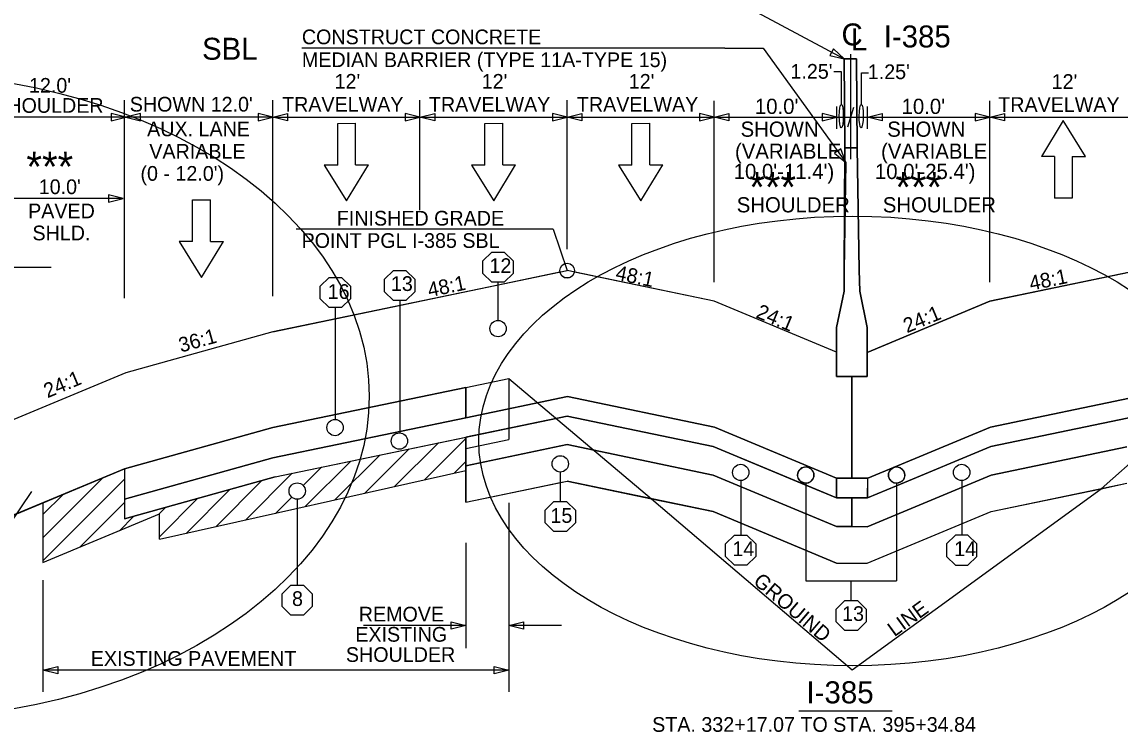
# Model space of a CAD drawing. Extents: x 4832 to 5477, y 4935 to 5220.
# Drawn here: x 5121.8 to 5211.3, y 5127.8 to 5185.7 of the extents above; entities that cross this region are included whole.
import ezdxf

# ---------------------------------------------------------------- set-up
doc = ezdxf.new("R2010")
doc.units = 0
for name, color, linetype in [('CLS_Clear_Zone', 7, 'Continuous'), ('Level 2', 7, 'Continuous'), ('RD_QTY_Milling', 7, 'Continuous'), ('RD_QTY_Miscl_1', 7, 'Continuous'), ('RD_SHT_Typical', 7, 'Continuous'), ('RD_TX_Misc1', 7, 'Continuous'), ('RD_TX_TypSect', 7, 'Continuous'), ('RD_XS_ExGround', 7, 'Continuous'), ('RD_XS_ExPaveRet', 7, 'Continuous'), ('RD_XS_PaveShd', 7, 'Continuous'), ('TERMINATOR', 7, 'Continuous'), ('typical_on', 7, 'Continuous')]:
    doc.layers.add(name, color=color, linetype=linetype)

# ---------------------------------------------------------------- blocks, each defined once
blk = doc.blocks.new('AH')
at = {"layer": 'TERMINATOR'}
blk.add_lwpolyline([(-6, 1.5), (0, 0), (-6, -1.5)], close=True, dxfattribs=at)

msp = doc.modelspace()

# ---------------------------------------------------------------- linework, layer by layer
at = {"layer": 'CLS_Clear_Zone'}
msp.add_line((5130.138, 5149.275), (5130.138, 5145.208), dxfattribs=at)
at = {"layer": 'Level 2'}
for p, q in [((5188.878, 5175.442), (5188.874, 5174.451)), ((5189.878, 5175.442), (5188.878, 5175.442)), ((5190.031, 5165.472), (5189.878, 5175.442)), ((5188.874, 5174.316), (5188.825, 5165.46))]:
    msp.add_line(p, q, dxfattribs=at)
msp.add_lwpolyline([(5188.878, 5175.442), (5188.822, 5182.719), (5189.822, 5182.719), (5189.878, 5175.442)], close=True, dxfattribs=at)
for points in [[(5189.878, 5175.442), (5189.822, 5182.719), (5188.822, 5182.719), (5188.878, 5175.442), (5189.878, 5175.442)], [(5188.825, 5165.46), (5188.878, 5175.442), (5189.878, 5175.442), (5190.031, 5165.472)], [(5188.874, 5174.451), (5188.958, 5174.252), (5188.874, 5174.316)], [(5190.031, 5165.472), (5190.101, 5163.767), (5190.701, 5160.803), (5190.701, 5156.803), (5188.201, 5156.803), (5188.201, 5160.803), (5188.801, 5163.767), (5188.825, 5165.46)]]:
    msp.add_lwpolyline(points, dxfattribs=at)
at = {"layer": 'RD_QTY_Milling'}
for p, q in [((5157.97, 5155.914), (5142.229, 5152.633)), ((5157.97, 5153.445), (5157.97, 5155.914)), ((5142.229, 5150.164), (5157.97, 5153.445)), ((5142.229, 5152.633), (5130.138, 5149.275)), ((5130.138, 5146.805), (5142.229, 5150.164)), ((5130.138, 5149.275), (5130.138, 5146.805))]:
    msp.add_line(p, q, dxfattribs=at)
msp.add_circle((5147.303, 5152.641), 0.666, dxfattribs=at)
at = {"layer": 'RD_QTY_Miscl_1'}
for p, q in [((5166.259, 5155.173), (5157.97, 5153.445)), ((5178.254, 5152.672), (5166.259, 5155.173)), ((5212.735, 5155.173), (5200.74, 5152.672)), ((5157.97, 5153.445), (5142.229, 5150.164)), ((5166.225, 5153.581), (5157.97, 5151.86)), ((5166.225, 5153.581), (5178.13, 5151.099)), ((5178.13, 5151.099), (5166.225, 5153.581)), ((5200.786, 5151.099), (5212.691, 5153.581)), ((5212.691, 5153.581), (5200.786, 5151.099)), ((5188.201, 5148.526), (5178.254, 5152.672)), ((5200.74, 5152.672), (5190.75, 5148.508)), ((5157.97, 5151.86), (5157.97, 5149.525)), ((5157.97, 5149.525), (5166.225, 5151.245)), ((5166.225, 5151.245), (5157.97, 5149.525)), ((5166.225, 5151.245), (5178.13, 5148.764)), ((5178.13, 5148.764), (5166.225, 5151.245)), ((5185.683, 5147.951), (5178.13, 5151.099)), ((5200.786, 5151.099), (5193.09, 5147.891)), ((5200.793, 5148.764), (5211.866, 5151.072)), ((5211.866, 5151.072), (5200.793, 5148.764)), ((5142.229, 5150.164), (5130.138, 5146.805)), ((5157.97, 5149.525), (5157.97, 5146.547)), ((5130.138, 5145.208), (5142.417, 5148.619)), ((5178.13, 5148.764), (5188.201, 5144.565)), ((5188.201, 5144.565), (5178.13, 5148.764)), ((5190.7, 5144.556), (5200.793, 5148.764)), ((5200.793, 5148.764), (5190.7, 5144.556)), ((5190.709, 5148.508), (5190.715, 5146.901)), ((5188.201, 5146.901), (5185.683, 5147.951)), ((5193.09, 5147.891), (5190.715, 5146.901)), ((5130.138, 5146.805), (5130.138, 5145.208)), ((5189.435, 5146.901), (5188.201, 5146.901)), ((5190.715, 5146.901), (5189.435, 5146.901)), ((5189.435, 5146.855), (5189.435, 5144.567)), ((5189.435, 5144.567), (5189.435, 5146.855)), ((5178.13, 5145.786), (5188.197, 5141.589)), ((5190.696, 5141.576), (5200.793, 5145.786)), ((5188.201, 5144.565), (5189.435, 5144.561)), ((5189.435, 5144.561), (5190.7, 5144.556)), ((5188.197, 5141.589), (5190.696, 5141.576))]:
    msp.add_line(p, q, dxfattribs=at)
for points in [[(5142.417, 5148.619), (5157.97, 5151.86), (5166.225, 5153.581)], [(5178.13, 5151.099), (5185.683, 5147.951), (5188.201, 5146.901)], [(5190.715, 5146.901), (5193.09, 5147.891), (5200.786, 5151.099)], [(5188.201, 5146.901), (5188.201, 5148.508), (5188.201, 5148.526)], [(5190.75, 5148.508), (5190.709, 5148.508)], [(5157.97, 5146.547), (5165.662, 5148.15), (5166.225, 5148.267)], [(5166.225, 5148.267), (5173.099, 5146.834), (5178.13, 5145.786)], [(5200.793, 5145.786), (5209.764, 5147.656), (5211.866, 5148.094)], [(5189.435, 5146.901), (5189.435, 5146.855)], [(5189.435, 5146.855), (5189.435, 5146.901)], [(5190.7, 5144.556), (5189.435, 5144.561), (5188.201, 5144.565)], [(5189.435, 5144.567), (5189.435, 5144.561)], [(5189.435, 5144.561), (5189.435, 5144.567)]]:
    msp.add_lwpolyline(points, dxfattribs=at)
for centre in [(5152.545, 5151.54), (5165.662, 5149.681), (5180.378, 5148.978), (5185.683, 5148.76), (5193.09, 5148.76), (5198.395, 5148.978)]:
    msp.add_circle(centre, 0.666, dxfattribs=at)
at = {"layer": 'RD_SHT_Typical'}
for p, q in [((5142.234, 5160.441), (5130.239, 5157.109)), ((5142.229, 5152.633), (5130.138, 5149.275)), ((5142.229, 5150.164), (5130.138, 5146.805)), ((5130.138, 5149.275), (5120.142, 5145.11)), ((5142.417, 5148.619), (5130.138, 5145.208))]:
    msp.add_line(p, q, dxfattribs=at)
at = {"layer": 'RD_TX_Misc1'}
for p, q in [((5147.517, 5177.451), (5148.973, 5177.46)), ((5147.517, 5174.051), (5147.517, 5177.451)), ((5148.973, 5174.06), (5148.973, 5177.46)), ((5159.512, 5177.451), (5160.969, 5177.46)), ((5159.512, 5174.051), (5159.512, 5177.451)), ((5160.969, 5174.06), (5160.969, 5177.46)), ((5171.507, 5177.451), (5172.964, 5177.46)), ((5171.507, 5174.051), (5171.507, 5177.451)), ((5172.964, 5174.06), (5172.964, 5177.46)), ((5206.679, 5177.673), (5204.895, 5174.749)), ((5208.501, 5174.759), (5206.679, 5177.673)), ((5205.952, 5174.749), (5204.895, 5174.749)), ((5205.952, 5174.749), (5205.952, 5171.349)), ((5207.409, 5174.759), (5208.501, 5174.759)), ((5207.409, 5174.759), (5207.409, 5171.358)), ((5147.517, 5174.051), (5146.424, 5174.05)), ((5146.424, 5174.05), (5148.246, 5171.136)), ((5148.246, 5171.136), (5150.03, 5174.06)), ((5148.973, 5174.06), (5150.03, 5174.06)), ((5159.512, 5174.051), (5158.419, 5174.05)), ((5158.419, 5174.05), (5160.241, 5171.136)), ((5160.241, 5171.136), (5162.025, 5174.06)), ((5160.969, 5174.06), (5162.025, 5174.06)), ((5171.507, 5174.051), (5170.414, 5174.05)), ((5170.414, 5174.05), (5172.237, 5171.136)), ((5172.237, 5171.136), (5174.02, 5174.06)), ((5172.964, 5174.06), (5174.02, 5174.06)), ((5135.687, 5171.206), (5137.145, 5171.215)), ((5135.687, 5167.802), (5135.687, 5171.206)), ((5137.145, 5167.812), (5137.145, 5171.215)), ((5207.409, 5171.358), (5205.952, 5171.349)), ((5135.687, 5167.802), (5134.593, 5167.802)), ((5134.593, 5167.802), (5136.417, 5164.885)), ((5136.417, 5164.885), (5138.202, 5167.812)), ((5137.145, 5167.812), (5138.202, 5167.812))]:
    msp.add_line(p, q, dxfattribs=at)
at = {"layer": 'RD_TX_TypSect'}
for p, q in [((5179.076, 5183.571), (5144.595, 5183.571)), ((5189.353, 5174.544), (5189.353, 5183.108)), ((5188.593, 5181.649), (5187.964, 5181.649)), ((5188.593, 5179.002), (5188.593, 5181.649)), ((5190.215, 5179.002), (5190.215, 5181.581)), ((5190.215, 5181.581), (5190.8, 5181.581)), ((5130.138, 5163.2), (5130.138, 5179.34)), ((5142.229, 5163.348), (5142.229, 5179.34)), ((5154.224, 5170.384), (5154.224, 5179.34)), ((5166.22, 5167.177), (5166.22, 5179.34)), ((5178.215, 5164.49), (5178.215, 5179.289)), ((5200.701, 5164.49), (5200.701, 5179.289)), ((5188.211, 5177.013), (5188.211, 5178.829)), ((5189.109, 5177.16), (5189.592, 5178.771)), ((5190.705, 5177.013), (5190.705, 5178.829)), ((5130.234, 5177.967), (5118.238, 5177.967)), ((5142.229, 5177.968), (5130.234, 5177.967)), ((5142.229, 5177.968), (5154.224, 5177.968)), ((5154.224, 5177.968), (5166.22, 5177.968)), ((5166.22, 5177.968), (5178.215, 5177.968)), ((5178.215, 5177.968), (5188.211, 5177.968)), ((5188.211, 5177.968), (5190.705, 5177.968)), ((5190.705, 5177.968), (5200.701, 5177.968)), ((5200.701, 5177.968), (5212.696, 5177.968)), ((5188.878, 5175.442), (5188.874, 5174.451)), ((5189.353, 5175.442), (5188.878, 5175.442)), ((5189.878, 5175.442), (5189.353, 5175.442)), ((5190.031, 5165.472), (5189.878, 5175.442)), ((5188.874, 5174.451), (5188.958, 5174.252)), ((5188.958, 5174.252), (5188.825, 5165.46)), ((5130.03, 5171.331), (5120.047, 5171.331)), ((5165.073, 5168.83), (5144.124, 5168.83)), ((5165.073, 5168.83), (5166.225, 5165.442)), ((5124.154, 5165.696), (5120.156, 5165.696)), ((5142.234, 5160.441), (5166.225, 5165.442)), ((5178.22, 5162.941), (5166.225, 5165.442)), ((5178.22, 5162.941), (5166.812, 5165.319)), ((5200.703, 5162.941), (5212.699, 5165.442)), ((5212.112, 5165.319), (5200.703, 5162.941)), ((5160.591, 5161.378), (5160.591, 5164.497)), ((5152.571, 5162.999), (5152.572, 5152.206)), ((5188.201, 5158.78), (5178.22, 5162.941)), ((5188.201, 5158.78), (5178.22, 5162.941)), ((5190.701, 5158.771), (5200.703, 5162.941)), ((5200.703, 5162.941), (5190.701, 5158.771)), ((5147.32, 5162.42), (5147.32, 5153.307)), ((5142.234, 5160.441), (5130.239, 5157.109)), ((5188.201, 5158.78), (5188.201, 5156.803)), ((5130.239, 5157.109), (5120.142, 5152.902)), ((5188.201, 5156.803), (5189.435, 5156.803)), ((5189.435, 5156.803), (5189.435, 5148.513)), ((5189.435, 5148.517), (5189.435, 5156.803)), ((5189.435, 5156.803), (5189.435, 5148.517)), ((5189.435, 5156.803), (5190.701, 5156.803)), ((5142.229, 5152.633), (5157.97, 5155.914)), ((5142.229, 5152.633), (5157.97, 5155.914)), ((5157.97, 5155.914), (5157.97, 5153.438)), ((5157.97, 5155.914), (5157.97, 5153.445)), ((5157.97, 5153.445), (5166.259, 5155.173)), ((5157.97, 5153.445), (5166.259, 5155.173)), ((5166.259, 5155.173), (5157.97, 5153.445)), ((5178.254, 5152.672), (5166.259, 5155.173)), ((5166.259, 5155.173), (5178.254, 5152.672)), ((5178.254, 5152.672), (5166.259, 5155.173)), ((5200.74, 5152.672), (5212.735, 5155.173)), ((5200.74, 5152.672), (5212.735, 5155.173)), ((5142.229, 5150.164), (5157.97, 5153.445)), ((5157.97, 5153.445), (5142.229, 5150.164)), ((5142.417, 5148.619), (5166.225, 5153.581)), ((5178.13, 5151.099), (5166.225, 5153.581)), ((5166.225, 5153.581), (5178.13, 5151.099)), ((5200.786, 5151.099), (5212.691, 5153.581)), ((5130.138, 5149.275), (5142.229, 5152.633)), ((5188.201, 5148.526), (5178.254, 5152.672)), ((5178.254, 5152.672), (5188.201, 5148.526)), ((5188.201, 5148.526), (5178.254, 5152.672)), ((5190.75, 5148.508), (5200.74, 5152.672)), ((5190.75, 5148.508), (5200.74, 5152.672)), ((5157.97, 5149.525), (5157.97, 5151.86)), ((5157.97, 5149.525), (5166.225, 5151.245)), ((5178.13, 5148.764), (5166.225, 5151.245)), ((5188.201, 5146.901), (5178.13, 5151.099)), ((5190.715, 5146.901), (5200.786, 5151.099)), ((5200.793, 5148.764), (5211.866, 5151.072)), ((5142.229, 5150.164), (5130.138, 5146.805)), ((5157.97, 5146.547), (5157.97, 5149.525)), ((5130.138, 5145.208), (5142.417, 5148.619)), ((5165.662, 5149.015), (5165.662, 5146.612)), ((5188.201, 5144.565), (5178.13, 5148.764)), ((5188.201, 5148.526), (5190.75, 5148.508)), ((5189.435, 5148.513), (5188.201, 5148.526)), ((5188.201, 5148.526), (5188.201, 5146.901)), ((5188.201, 5148.526), (5189.435, 5148.517)), ((5188.201, 5146.901), (5188.201, 5148.526)), ((5190.75, 5148.508), (5189.435, 5148.513)), ((5190.7, 5144.556), (5200.793, 5148.764)), ((5190.715, 5146.901), (5190.75, 5148.508)), ((5157.97, 5146.547), (5166.225, 5148.267)), ((5178.13, 5145.786), (5166.225, 5148.267)), ((5180.378, 5148.312), (5180.378, 5143.877)), ((5185.225, 5148.276), (5185.683, 5148.094)), ((5185.683, 5148.094), (5185.683, 5140.128)), ((5193.09, 5148.094), (5193.542, 5148.27)), ((5193.09, 5148.094), (5193.09, 5140.128)), ((5198.395, 5148.312), (5198.395, 5143.877)), ((5200.793, 5145.786), (5211.866, 5148.094)), ((5130.138, 5146.805), (5130.138, 5145.208)), ((5144.213, 5146.798), (5144.213, 5139.795)), ((5188.201, 5146.901), (5190.715, 5146.901)), ((5188.201, 5146.901), (5189.435, 5146.901)), ((5189.435, 5146.901), (5190.715, 5146.901)), ((5161.469, 5146.502), (5161.469, 5131.095)), ((5188.197, 5141.589), (5178.13, 5145.786)), ((5190.696, 5141.576), (5200.793, 5145.786)), ((5188.201, 5144.565), (5190.7, 5144.556)), ((5157.97, 5143.25), (5157.97, 5134.642)), ((5188.197, 5141.589), (5190.696, 5141.576)), ((5123.484, 5140.205), (5123.484, 5131.095)), ((5185.683, 5140.128), (5189.386, 5140.128)), ((5189.386, 5138.542), (5189.386, 5140.128)), ((5189.386, 5140.128), (5193.09, 5140.128)), ((5157.97, 5136.505), (5149.633, 5136.505)), ((5165.757, 5136.505), (5161.469, 5136.505)), ((5161.469, 5132.864), (5123.484, 5132.864)), ((5185.105, 5129.529), (5192.719, 5129.529))]:
    msp.add_line(p, q, dxfattribs=at)
for points in [[(5177.793, 5187.369), (5180.124, 5187.369), (5188.822, 5182.719)], [(5179.076, 5183.571), (5182.221, 5183.571), (5188.958, 5174.252)], [(5190.701, 5156.803), (5190.701, 5158.771), (5190.701, 5160.803), (5190.101, 5163.767), (5190.031, 5165.472)], [(5165.638, 5165.319), (5160.591, 5164.267), (5142.234, 5160.441)], [(5188.825, 5165.46), (5188.801, 5163.767), (5188.201, 5160.803), (5188.201, 5158.78)], [(5189.435, 5156.803), (5188.201, 5156.803), (5188.201, 5158.78)], [(5190.701, 5158.771), (5190.701, 5156.803), (5189.435, 5156.803)], [(5142.417, 5148.619), (5157.97, 5151.86), (5166.225, 5153.581)], [(5178.13, 5151.099), (5185.683, 5147.951), (5188.201, 5146.901)], [(5120.143, 5145.11), (5121.344, 5145.611), (5130.138, 5149.275)], [(5189.435, 5148.517), (5189.435, 5148.517), (5190.75, 5148.508)]]:
    msp.add_lwpolyline(points, dxfattribs=at)
for points in [[(5187.654, 5182.991), (5188.822, 5182.719), (5187.947, 5183.539)], [(5188.027, 5175.009), (5188.958, 5174.252), (5188.531, 5175.373)]]:
    msp.add_lwpolyline(points, close=True, dxfattribs=at)
for centre, radius in [((5166.225, 5165.442), 0.6), ((5160.591, 5160.712), 0.666), ((5160.591, 5160.712), 0.666), ((5160.591, 5160.712), 0.666), ((5147.303, 5152.641), 0.666), ((5147.303, 5152.641), 0.666), ((5152.545, 5151.54), 0.666), ((5152.545, 5151.54), 0.666), ((5165.662, 5149.681), 0.666), ((5165.662, 5149.681), 0.666), ((5180.378, 5148.978), 0.666), ((5180.378, 5148.978), 0.666), ((5185.683, 5148.76), 0.666), ((5185.683, 5148.76), 0.666), ((5193.09, 5148.76), 0.666), ((5198.395, 5148.978), 0.666), ((5198.395, 5148.978), 0.666), ((5144.213, 5147.465), 0.666), ((5144.213, 5147.465), 0.666)]:
    msp.add_circle(centre, radius, dxfattribs=at)
for centre, radius, start, end in [((5166.225, 5165.442), 0.6, 191.77401, 348.22599), ((5185.683, 5148.76), 0.666, 270, 226.59763), ((5193.09, 5148.76), 0.666, 312.66773, 270)]:
    msp.add_arc(centre, radius, start, end, dxfattribs=at)
for centre, major_axis, ratio in [((5111.468, 5155.19), (38.618, 0), 0.681891), ((5188.581, 5178.049), (0.008, 0.953), 0.172853), ((5190.203, 5178.049), (0.008, 0.953), 0.172853), ((5189.511, 5151.547), (30.489, 0), 0.60143)]:
    msp.add_ellipse(centre, major_axis=major_axis, ratio=ratio, dxfattribs=at)
at = {"layer": 'RD_XS_ExGround'}
for p, q in [((5189.458, 5132.868), (5209.764, 5147.656)), ((5117.333, 5139.673), (5122.573, 5147.429)), ((5173.099, 5146.834), (5189.458, 5132.868))]:
    msp.add_line(p, q, dxfattribs=at)
at = {"layer": 'RD_XS_ExPaveRet'}
for p, q in [((5157.97, 5155.914), (5161.469, 5156.644)), ((5161.469, 5156.644), (5161.469, 5151.665)), ((5161.469, 5156.644), (5173.099, 5146.834)), ((5216.947, 5153.987), (5209.764, 5147.656)), ((5152.153, 5147.823), (5155.722, 5151.392)), ((5154.583, 5148.367), (5157.97, 5151.755)), ((5157.97, 5150.935), (5161.469, 5151.665)), ((5147.294, 5146.733), (5150.96, 5150.399)), ((5149.724, 5147.278), (5153.341, 5150.896)), ((5157.97, 5150.935), (5157.97, 5149.127)), ((5144.705, 5147.914), (5146.197, 5149.407)), ((5144.865, 5146.189), (5148.579, 5149.903)), ((5157.012, 5148.912), (5157.97, 5149.87)), ((5123.484, 5143.657), (5128.361, 5148.535)), ((5123.484, 5141.772), (5130.166, 5148.454)), ((5132.98, 5143.525), (5157.97, 5149.127)), ((5140.006, 5145.1), (5143.816, 5148.91)), ((5135.147, 5144.01), (5138.731, 5147.595)), ((5137.576, 5144.555), (5141.341, 5148.32)), ((5123.484, 5145.542), (5125.13, 5147.188)), ((5132.98, 5143.729), (5136.121, 5146.87)), ((5142.435, 5145.644), (5143.764, 5146.973)), ((5123.484, 5146.502), (5123.484, 5141.634)), ((5126.479, 5142.882), (5130.15, 5146.553)), ((5132.944, 5145.578), (5133.511, 5146.145)), ((5123.484, 5141.634), (5132.98, 5145.593)), ((5129.712, 5144.23), (5130.901, 5145.42)), ((5132.98, 5143.525), (5132.98, 5145.593))]:
    msp.add_line(p, q, dxfattribs=at)
at = {"layer": 'RD_XS_PaveShd'}
msp.add_line((5130.239, 5157.109), (5120.142, 5152.902), dxfattribs=at)
at = {"layer": 'typical_on'}
for points in [[(5161.822, 5166.238), (5161.822, 5165.218), (5161.101, 5164.497), (5160.081, 5164.497), (5159.36, 5165.218), (5159.36, 5166.237), (5160.081, 5166.959), (5161.101, 5166.959)], [(5148.551, 5164.161), (5148.551, 5163.142), (5147.83, 5162.42), (5146.81, 5162.42), (5146.089, 5163.141), (5146.089, 5164.161), (5146.81, 5164.882), (5147.83, 5164.882)], [(5153.802, 5164.74), (5153.802, 5163.72), (5153.081, 5162.999), (5152.061, 5162.999), (5151.34, 5163.72), (5151.34, 5164.74), (5152.061, 5165.461), (5153.081, 5165.461)], [(5166.893, 5145.891), (5166.893, 5144.871), (5166.172, 5144.15), (5165.152, 5144.15), (5164.431, 5144.871), (5164.431, 5145.891), (5165.152, 5146.612), (5166.172, 5146.612)], [(5181.609, 5143.156), (5181.609, 5142.136), (5180.888, 5141.415), (5179.868, 5141.415), (5179.147, 5142.136), (5179.147, 5143.156), (5179.868, 5143.877), (5180.888, 5143.877)], [(5197.164, 5143.156), (5197.164, 5142.136), (5197.885, 5141.415), (5198.905, 5141.415), (5199.626, 5142.136), (5199.626, 5143.156), (5198.905, 5143.877), (5197.885, 5143.877)], [(5145.444, 5139.074), (5145.444, 5138.054), (5144.723, 5137.333), (5143.703, 5137.333), (5142.982, 5138.054), (5142.982, 5139.074), (5143.703, 5139.795), (5144.723, 5139.795)], [(5190.617, 5137.821), (5190.617, 5136.801), (5189.896, 5136.08), (5188.877, 5136.08), (5188.156, 5136.801), (5188.156, 5137.821), (5188.877, 5138.542), (5189.896, 5138.542)]]:
    msp.add_lwpolyline(points, close=True, dxfattribs=at)

# ---------------------------------------------------------------- block references
at = {"layer": 'TERMINATOR'}
for p, xscale, yscale, rotation in [((5130.234, 5177.967), 0.2000217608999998, -0.20002176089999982, 0.0014178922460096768), ((5130.234, 5177.967), 0.20002176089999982, -0.20002176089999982, -179.99858211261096), ((5142.229, 5177.968), 0.20002176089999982, -0.20002176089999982, 0.0014178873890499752), ((5142.229, 5177.968), 0.2000217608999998, 0.2000217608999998, 180), ((5154.224, 5177.968), 0.2000217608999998, 0.2000217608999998, 180), ((5166.22, 5177.968), 0.2000217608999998, 0.2000217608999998, 180), ((5178.215, 5177.968), 0.2000217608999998, 0.2000217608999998, 180), ((5190.705, 5177.968), 0.2000217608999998, 0.2000217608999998, 180), ((5200.701, 5177.968), 0.2000217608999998, 0.2000217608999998, 180), ((5161.469, 5136.505), 0.1999217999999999, 0.1999217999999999, 180), ((5123.484, 5132.864), 0.1999217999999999, 0.1999217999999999, 180)]:
    msp.add_blockref('AH', p, dxfattribs=dict(at, xscale=xscale, yscale=yscale, rotation=rotation))
for p, xscale, yscale in [((5154.224, 5177.968), 0.2000217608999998, -0.2000217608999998), ((5166.22, 5177.968), 0.2000217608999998, -0.2000217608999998), ((5178.215, 5177.968), 0.2000217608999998, -0.2000217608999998), ((5188.211, 5177.968), 0.2000217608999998, -0.2000217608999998), ((5200.701, 5177.968), 0.2000217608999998, -0.2000217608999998), ((5130.03, 5171.331), 0.2000217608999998, -0.2000217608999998), ((5157.97, 5136.505), 0.1999217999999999, 0.1999217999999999), ((5161.469, 5132.864), 0.1999217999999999, 0.1999217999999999)]:
    msp.add_blockref('AH', p, dxfattribs=dict(at, xscale=xscale, yscale=yscale))

# ---------------------------------------------------------------- texts
at = {"layer": 'RD_TX_TypSect'}
for s, height, p in [('C', 1.791, (5188.597, 5183.808)), ('L', 1.791, (5189.357, 5183.405)), ('I-385', 1.7909, (5192.044, 5183.643)), ('SBL', 1.7909, (5136.457, 5182.64)), ('CONSTRUCT CONCRETE', 1.2, (5144.596, 5183.904)), ('MEDIAN BARRIER (TYPE 11A-TYPE 15)', 1.2, (5144.596, 5182.038)), ("1.25'", 1.2, (5184.435, 5181.093)), ("1.25'", 1.2, (5190.741, 5181.059)), ("12'", 1.2, (5147.262, 5180.276)), ("12'", 1.2, (5159.257, 5180.276)), ("12'", 1.2, (5171.252, 5180.276)), ("12'", 1.2, (5205.733, 5180.263)), ('SHOULDER', 1.2, (5119.508, 5178.311)), ("10.0'", 1.2407, (5181.535, 5178.219)), ("10.0'", 1.2407, (5193.495, 5178.219)), ('SHOWN', 1.2407, (5180.367, 5176.358)), ('SHOWN', 1.2407, (5192.327, 5176.358)), ('VARIABLE', 1.2, (5132.156, 5174.57)), ('(VARIABLE', 1.2407, (5179.911, 5174.561)), ('(VARIABLE', 1.2407, (5191.822, 5174.561)), ('***', 2.4431, (5122.133, 5172.702)), ("(0 - 12.0')", 1.2, (5131.433, 5172.77)), ("10.0'-11.4')", 1.24068, (5179.805, 5172.91)), ("10.0'-25.4')", 1.24068, (5191.321, 5172.91)), ('***', 2.4431, (5181.075, 5171.036)), ('***', 2.4431, (5192.987, 5171.036)), ('SHOULDER', 1.2407, (5180.054, 5170.189)), ('SHOULDER', 1.2407, (5191.965, 5170.189)), ('12', 1.2, (5159.893, 5165.247)), ('13', 1.2, (5151.857, 5163.78)), ('16', 1.2, (5146.696, 5163.133)), ('15', 1.2, (5164.864, 5144.867)), ('14', 1.2, (5179.702, 5142.155)), ('14', 1.2, (5197.786, 5142.155)), ('8', 1.2, (5143.789, 5138.088)), ('13', 1.2, (5188.648, 5136.866)), ('I-385', 1.8, (5185.733, 5130.145)), ('STA. 332+17.07 TO STA. 395+34.84', 1.2, (5173.158, 5127.823))]:
    msp.add_text(s, height=height, dxfattribs=at).set_placement(p)
for s, height, rotation, p in [("12.0'", 1.2, 0.00071, (5122.344, 5179.95)), ("SHOWN 12.0'", 1.2, 0.00071, (5130.563, 5178.412)), ('TRAVELWAY', 1.2, 359.99858, (5142.981, 5178.399)), ('TRAVELWAY', 1.2, 359.99858, (5154.954, 5178.399)), ('TRAVELWAY', 1.2, 359.99858, (5167.02, 5178.399)), ('TRAVELWAY', 1.2, 359.99858, (5201.378, 5178.386)), ('AUX. LANE', 1.2, 359.99858, (5131.977, 5176.399)), ("10.0'", 1.2, 359.99858, (5123.14, 5171.681)), ('PAVED', 1.2, 359.99858, (5122.273, 5169.708)), ('FINISHED GRADE', 1.20007, 360, (5147.443, 5169.114)), ('SHLD.', 1.2, 359.99858, (5122.627, 5167.911)), ('POINT PGL I-385 SBL', 1.20007, 360, (5144.571, 5167.294)), ('48:1', 1.2, 348.32401, (5170.108, 5164.716)), ('48:1', 1.2, 11.67599, (5204.043, 5163.802)), ('48:1', 1.2, 11.67599, (5154.986, 5163.266)), ('24:1', 1.2, 337.38196, (5181.543, 5161.646)), ('24:1', 1.2, 22.61804, (5193.939, 5160.329)), ('36:1', 1.2, 15.52411, (5134.735, 5158.753)), ('24:1', 1.2, 22.61986, (5123.847, 5155.023)), ('GROUIND', 1.2, 319.51056, (5181.324, 5139.97)), ('REMOVE', 1.2, 360, (5149.234, 5136.822)), ('LINE', 1.2, 36.0635, (5192.912, 5135.532)), ('EXISTING', 1.2, 360, (5148.95, 5135.174)), ('EXISTING PAVEMENT', 1.2, 360, (5127.384, 5133.206)), ('SHOULDER', 1.2, 360, (5148.185, 5133.526))]:
    msp.add_text(s, height=height, rotation=rotation, dxfattribs=at).set_placement(p)

doc.saveas('drawing.dxf')
